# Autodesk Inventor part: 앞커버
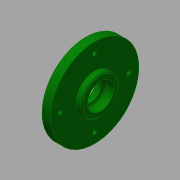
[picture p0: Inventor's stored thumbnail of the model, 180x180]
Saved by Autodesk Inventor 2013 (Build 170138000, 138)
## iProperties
Created: 2015-09
Part Number: 앞커버
Material: 알루미늄 6061
Document SubType Name: Modeling
Designer: mduedu
Density: 2.71 g/cm^3
Mass: 58.9874 g
Surface Area: 98.7754 cm^2
Volume: 21.7666 cm^3
Author: mduedu
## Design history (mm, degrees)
sketch "스케치1"
  geometry: L1 (-6.5, 63)-(-11.5, 63); L2 (-11.5, 63)-(-11.5, 84.5); L3 (-11.5, 84.5)-(-19.5, 84.5); L4 (-19.5, 84.5)-(-19.5, 70.5); L5 (-24.5, 70.5)-(-24.5, 54.5); L6 (-24.5, 54.5)-(-6.5, 54.5); L7 (-6.5, 54.5)-(-6.5, 63); L8 (-79.5, 39.5)-(-79.5, 54.5) reference; L9 (48.5, 54.5)-(48.5, 39.5) reference; L10 (-79.5, 47)-(48.5, 47); L11 (-19.5, 70.5)-(-24.5, 70.5); 3 further points
  constraints: 18 end point, 6 parallel, 4 midpoint, 1 horizontal, 1 perpendicular, 1 vertical alignment
  dimensions: "d0" = 18 distance between parallel lines of L7 L5; "d3" = 32 diameter of L1 L10; "d5" = 5 distance of L1.start L1.end; "d6" = 75 diameter of L3 L10; "d7" = 8 distance of L2.end L3.end; "d8" = 47 diameter of L4.end L10; "d61" = 15 diameter of L6 L10
revolve "회전1" sketch "스케치1" stored, may be unused: angle "d4" = 90 deg
sketch "스케치2"
  geometry: C1 r 37.5 at (0, 0) reference; 2 further points
  constraints: 1 coincident
hole "구멍1" sketch "스케치2" at (0, 0) diameter "d11" = 22; stored, may be unused: countersink angle "d15" = 90 deg, drill point angle "d17" = 0 deg; dims "d12" = 6, "d13" = 4, "d14" = 2, "d16" = 8
fillet "모깎기1" dims "d18" = 3
fillet "모깎기2" dims "d19" = 1
sketch "스케치3"
  geometry: C1 r 37.5 at (0, 0) reference; 2 further points
  constraints: 1 coincident
hole "구멍2" sketch "스케치3" at (0, 0) diameter "d20" = 30; stored, may be unused: countersink angle "d24" = 90 deg, drill point angle "d26" = 0 deg; dims "d21" = 6, "d22" = 4, "d23" = 2, "d25" = 7.5
fillet "모깎기3" dims "d27" = 0.3
chamfer "모따기1" distance "d28" = 1; stored, may be unused: second distance "d29" = 2, angle "d30" = 30 deg
sketch "스케치7" dims "d56" = 58
  geometry: C1 r 37.5 at (0, 0) reference; 5 further points
  constraints: 2 vertical alignment, 1 coincident, 7 other
  dimensions: "d59" = 360 deg dimension on C1.centre point (0, 29) (derived)
hole "구멍4" sketch "스케치7" at (0, 29), (-29, 0), (0, -29), (29, 0) diameter "d48" = 3.4; stored, may be unused: countersink angle "d52" = 90 deg, drill point angle "d54" = 0 deg; dims "d49" = 6, "d50" = 6.5, "d51" = 3.4, "d53" = 8
hole "구멍5" diameter "d64" = 17; stored, may be unused: countersink angle "d68" = 90 deg, drill point angle "d70" = 118 deg; dims "d62" = 10, "d63" = 10, "d65" = 6, "d66" = 4, "d67" = 2, "d69" = 8
chamfer "모따기2" distance "d71" = 1; stored, may be unused: second distance "d72" = 2, angle "d73" = 45 deg
node "솔리드1"
node "참조1"
node "참조2"
